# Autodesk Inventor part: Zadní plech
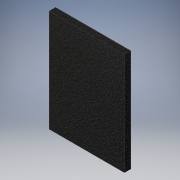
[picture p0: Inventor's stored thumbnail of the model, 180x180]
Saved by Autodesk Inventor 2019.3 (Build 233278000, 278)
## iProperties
Created: 2019-02
Part Number: Zadní plech
Material: Ocel, měkká, svařovaná
Document SubType Name: Modeling
Designer: B-hon
Density: 7.85 g/cm^3
Appearance: Černý – litý
Author: B-hon
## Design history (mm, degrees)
sketch "Náčrt1"
  geometry: L1 (0, 0)-(70, 0); L2 (70, 0)-(70, 95); L3 (70, 95)-(0, 95); L4 (0, 95)-(0, 0)
  constraints: 8 end point, 2 parallel, 1 horizontal, 1 perpendicular
  dimensions: "d0" = 70 distance of L3.end L2.end; "d1" = 95 distance of L2.end L1.end
extrude "Vysunutí1" new body sketch "Náčrt1" distance "d2" = 6; taper "d3" = 0 deg
node "Těleso1"
